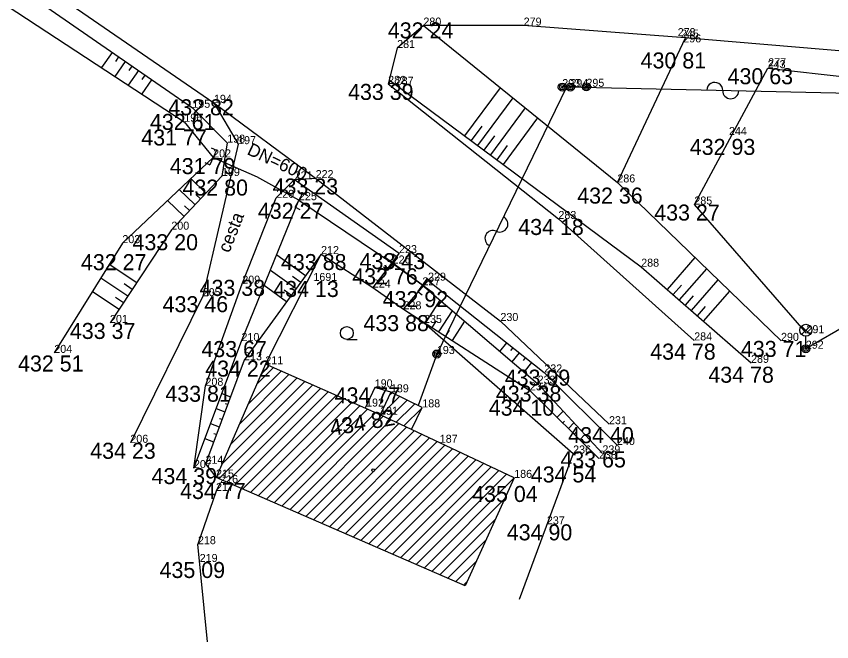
# Model space of a CAD drawing. Extents: x -559180 to -551373, y -1076947 to -1072071.
# Drawn here: x -554299 to -554248, y -1073863.4 to -1073824.3 of the extents above; entities that cross this region are included whole.
import ezdxf

# ---------------------------------------------------------------- set-up
doc = ezdxf.new("R2010")
doc.units = 0
for name, color, linetype in [('12_PLOTY', 7, 'Continuous'), ('14_BUDOVY', 7, 'Continuous'), ('17_KOMUNIKACE', 7, 'Continuous'), ('18_POLOHOPIS', 7, 'Continuous'), ('1_VODA_ZN', 7, 'Continuous'), ('20_EL_ZN', 7, 'Continuous'), ('26_SRAFY', 7, 'Continuous'), ('27_HRANA_PATA', 7, 'Continuous'), ('30_SDEL_ZN', 7, 'Continuous'), ('31_SDELOVACI', 7, 'Continuous'), ('32', 7, 'Continuous'), ('3_BODY', 7, 'Continuous'), ('40_KANAL_ZN', 7, 'Continuous'), ('45_ZN_KULTURY', 7, 'Continuous'), ('47_ZN_STAV_OBJ$', 7, 'Continuous'), ('49_POPIS_KANAL', 7, 'Continuous'), ('52_POPIS_UCELOVY', 7, 'Continuous'), ('6_VYSKY', 7, 'Continuous'), ('NNnadzemní', 7, 'Continuous')]:
    doc.layers.add(name, color=color, linetype=linetype)

# ---------------------------------------------------------------- blocks, each defined once
blk = doc.blocks.new('POINT_DISPLAY')
blk.add_line((0, 0), (0, 0))
blk = doc.blocks.new('SLDP')
at = {"layer": '20_EL_ZN'}
for radius in [0.25, 0.158, 0.05]:
    blk.add_circle((0, 0), radius, dxfattribs=at)
blk = doc.blocks.new('JS600')
at = {"layer": '49_POPIS_KANAL'}
blk.add_text('DN=600', height=0.8, rotation=0, dxfattribs=at).set_placement((0.752, -0.172))
blk = doc.blocks.new('LAO')
at = {"layer": '20_EL_ZN'}
for p, q in [((-0.265, 1.415), (0.265, 0.885)), ((-0.265, 0.885), (0.265, 1.415)), ((0, 0), (0, 0.775))]:
    blk.add_line(p, q, dxfattribs=at)
blk.add_circle((0, 1.15), 0.375, dxfattribs=at)
blk = doc.blocks.new('BZ')
at = {"layer": '47_ZN_STAV_OBJ$'}
blk.add_circle((0, 0), 0.0875, dxfattribs=at)
blk = doc.blocks.new('VYUST')
at = {"layer": '40_KANAL_ZN'}
for p, q in [((-0.35, 0.5), (0, 0.5)), ((0, 0.5), (0, -0.5)), ((0, 0), (3, 0.001)), ((-0.35, -0.5), (0, -0.5))]:
    blk.add_line(p, q, dxfattribs=at)
blk = doc.blocks.new('ZAHRAD')
at = {"layer": '45_ZN_KULTURY'}
blk.add_line((0, 0), (0.65, 0.003), dxfattribs=at)
blk.add_circle((0, 0.403), 0.403, dxfattribs=at)
blk = doc.blocks.new('SDEN')
at = {"layer": '30_SDEL_ZN'}
for centre, start, end in [((0.5, 0), 359.9999, 179.9999), ((1.5, 0), 179.9999, 359.9999)]:
    blk.add_arc(centre, 0.5, start, end, dxfattribs=at)

msp = doc.modelspace()

# ---------------------------------------------------------------- linework, layer by layer
at = {"layer": '12_PLOTY'}
for p, q in [((-554256.62, -1073836.08), (-554252.04, -1073827.57)), ((-554252.04, -1073827.57), (-554236.91, -1073829.29)), ((-554249.62, -1073844.11), (-554256.62, -1073836.08)), ((-554283.41, -1073846.05), (-554279.93, -1073839.17)), ((-554279.93, -1073839.17), (-554276.7, -1073841.26)), ((-554276.7, -1073841.26), (-554274.78, -1073842.62)), ((-554274.78, -1073842.62), (-554273.5, -1073843.47)), ((-554273.5, -1073843.47), (-554264.19, -1073851.62)), ((-554264.19, -1073851.62), (-554267.569, -1073860.727)), ((-554286.23, -1073853.46), (-554286.49, -1073853.96)), ((-554286.49, -1073853.96), (-554287.62, -1073857.28)), ((-554287.017, -1073863.365), (-554287.62, -1073857.28))]:
    msp.add_line(p, q, dxfattribs=at)
at = {"layer": '14_BUDOVY'}
for p, q in [((-554283.41, -1073846.05), (-554286.49, -1073853.12)), ((-554276.25, -1073849.2), (-554283.41, -1073846.05)), ((-554275.57, -1073847.8), (-554276.25, -1073849.2)), ((-554273.61, -1073848.74), (-554275.57, -1073847.8)), ((-554274.274, -1073850.124), (-554273.61, -1073848.74)), ((-554274.274, -1073850.124), (-554276.25, -1073849.2)), ((-554267.87, -1073853.14), (-554274.274, -1073850.124)), ((-554270.94, -1073859.88), (-554286.49, -1073853.12)), ((-554267.87, -1073853.14), (-554270.94, -1073859.88))]:
    msp.add_line(p, q, dxfattribs=at)
at = {"layer": '17_KOMUNIKACE'}
for p, q in [((-554320.63, -1073806.35), (-554286.62, -1073829.73)), ((-554273.54, -1073824.91), (-554275.18, -1073826.31)), ((-554267.28, -1073824.91), (-554273.54, -1073824.91)), ((-554257.46, -1073825.66), (-554267.28, -1073824.91)), ((-554236.82, -1073827.4), (-554257.46, -1073825.66)), ((-554275.18, -1073826.31), (-554275.74, -1073828.55)), ((-554275.74, -1073828.55), (-554265.11, -1073836.98)), ((-554286.62, -1073829.73), (-554285.11, -1073832.31)), ((-554286.62, -1073829.73), (-554280.27, -1073834.43)), ((-554285.11, -1073832.31), (-554287.32, -1073841.8)), ((-554282.73, -1073835.66), (-554281.58, -1073834.51)), ((-554281.58, -1073834.51), (-554280.27, -1073834.43)), ((-554280.27, -1073834.43), (-554268.73, -1073843.35)), ((-554284.85, -1073841.02), (-554282.73, -1073835.66)), ((-554265.11, -1073836.98), (-554256.63, -1073844.56)), ((-554287.15, -1073847.39), (-554284.85, -1073841.02)), ((-554287.32, -1073841.8), (-554291.84, -1073850.95)), ((-554268.73, -1073843.35), (-554261.95, -1073849.79)), ((-554287.87, -1073852.53), (-554287.15, -1073847.39))]:
    msp.add_line(p, q, dxfattribs=at)
at = {"layer": '18_POLOHOPIS'}
for p, q in [((-554276.58, -1073847.49), (-554277.168, -1073848.796)), ((-554275.57, -1073847.8), (-554276.58, -1073847.49))]:
    msp.add_line(p, q, dxfattribs=at)
at = {"layer": '26_SRAFY'}
for p, q in [((-554293.621, -1073827.532), (-554292.964, -1073826.583)), ((-554292.748, -1073827.149), (-554292.553, -1073826.867)), ((-554292.785, -1073828.081), (-554292.142, -1073827.152)), ((-554291.921, -1073827.712), (-554291.73, -1073827.437)), ((-554291.948, -1073828.629), (-554291.319, -1073827.721)), ((-554291.095, -1073828.275), (-554290.908, -1073828.006)), ((-554291.112, -1073829.178), (-554290.497, -1073828.29)), ((-554268.741, -1073828.789), (-554270.965, -1073831.79)), ((-554267.963, -1073829.419), (-554270.161, -1073832.386)), ((-554267.184, -1073830.048), (-554269.358, -1073832.981)), ((-554266.406, -1073830.677), (-554268.555, -1073833.576)), ((-554269.9, -1073831.193), (-554270.563, -1073832.088)), ((-554269.104, -1073831.798), (-554269.76, -1073832.683)), ((-554268.308, -1073832.404), (-554268.956, -1073833.279)), ((-554288.071, -1073834.462), (-554287.119, -1073835.36)), ((-554288.8, -1073835.149), (-554287.806, -1073836.087)), ((-554287.754, -1073835.448), (-554287.463, -1073835.723)), ((-554289.528, -1073835.837), (-554288.492, -1073836.814)), ((-554288.453, -1073836.163), (-554288.149, -1073836.451)), ((-554282.7, -1073839.214), (-554280.906, -1073840.515)), ((-554293.157, -1073839.807), (-554291.442, -1073840.936)), ((-554256.586, -1073839.388), (-554258.323, -1073841.374)), ((-554283.089, -1073840.167), (-554281.493, -1073841.325)), ((-554255.866, -1073840.084), (-554257.57, -1073842.033)), ((-554293.684, -1073840.657), (-554291.992, -1073841.771)), ((-554281.708, -1073840.551), (-554281.2, -1073840.92)), ((-554255.147, -1073840.781), (-554256.817, -1073842.691)), ((-554292.228, -1073841.017), (-554291.717, -1073841.353)), ((-554283.479, -1073841.12), (-554282.081, -1073842.134)), ((-554257.43, -1073841.113), (-554257.946, -1073841.704)), ((-554294.212, -1073841.507), (-554292.542, -1073842.606)), ((-554292.771, -1073841.857), (-554292.267, -1073842.189)), ((-554282.236, -1073841.404), (-554281.787, -1073841.73)), ((-554256.688, -1073841.783), (-554257.194, -1073842.362)), ((-554254.427, -1073841.477), (-554256.065, -1073843.349)), ((-554272.511, -1073842.05), (-554273.431, -1073843.485)), ((-554271.743, -1073842.705), (-554272.59, -1073844.025)), ((-554255.945, -1073842.453), (-554256.441, -1073843.02)), ((-554272.745, -1073843.342), (-554273.01, -1073843.755)), ((-554270.976, -1073843.361), (-554271.748, -1073844.565)), ((-554271.926, -1073843.916), (-554272.169, -1073844.295)), ((-554268.762, -1073845.251), (-554268.335, -1073844.709)), ((-554268.074, -1073845.186), (-554267.942, -1073845.019)), ((-554268.001, -1073845.901), (-554267.55, -1073845.329)), ((-554267.296, -1073845.815), (-554267.157, -1073845.639)), ((-554267.24, -1073846.551), (-554266.765, -1073845.949)), ((-554286.128, -1073847.879), (-554285.59, -1073848.08)), ((-554285.927, -1073848.488), (-554285.765, -1073848.548)), ((-554286.479, -1073848.815), (-554285.94, -1073849.016)), ((-554264.819, -1073848.968), (-554265.198, -1073849.352)), ((-554286.277, -1073849.425), (-554286.115, -1073849.485)), ((-554286.83, -1073849.752), (-554286.289, -1073849.953)), ((-554264.733, -1073849.593), (-554264.843, -1073849.703)), ((-554264.137, -1073849.701), (-554264.487, -1073850.055)), ((-554286.626, -1073850.361), (-554286.464, -1073850.422)), ((-554264.031, -1073850.305), (-554264.132, -1073850.406)), ((-554263.455, -1073850.433), (-554263.776, -1073850.758)), ((-554287.18, -1073850.688), (-554286.639, -1073850.89))]:
    msp.add_line(p, q, dxfattribs=at)
at = {"layer": '27_HRANA_PATA'}
for p, q in [((-554326.55, -1073803.33), (-554287.97, -1073830.04)), ((-554327.69, -1073805.19), (-554288.47, -1073830.91)), ((-554273.54, -1073824.91), (-554261.43, -1073834.7)), ((-554261.43, -1073834.7), (-554257.18, -1073825.684)), ((-554275.677, -1073828.298), (-554259.94, -1073839.96)), ((-554287.97, -1073830.04), (-554285.79, -1073832.22)), ((-554288.47, -1073830.91), (-554286.67, -1073833.14)), ((-554285.79, -1073832.22), (-554286.12, -1073834.3)), ((-554286.67, -1073833.14), (-554292.34, -1073838.49)), ((-554286.12, -1073834.3), (-554289.28, -1073837.65)), ((-554281.58, -1073834.51), (-554275.06, -1073839.11)), ((-554261.43, -1073834.7), (-554251.21, -1073844.59)), ((-554284.9, -1073844.6), (-554281.31, -1073835.81)), ((-554281.31, -1073835.81), (-554275.46, -1073839.76)), ((-554289.28, -1073837.65), (-554293.11, -1073843.47)), ((-554292.34, -1073838.49), (-554296.59, -1073845.34)), ((-554279.93, -1073839.17), (-554284.74, -1073845.8)), ((-554275.06, -1073839.11), (-554276.7, -1073841.26)), ((-554259.94, -1073839.96), (-554253.08, -1073845.96)), ((-554274.78, -1073842.62), (-554273.25, -1073840.83)), ((-554273.25, -1073840.83), (-554265.99, -1073846.56)), ((-554273.6, -1073841.12), (-554266.41, -1073847.26)), ((-554274.78, -1073842.62), (-554266.89, -1073847.68)), ((-554287.87, -1073852.53), (-554284.9, -1073844.6)), ((-554284.74, -1073845.8), (-554287.15, -1073852.26)), ((-554265.99, -1073846.56), (-554261.45, -1073851.09)), ((-554266.41, -1073847.26), (-554262.36, -1073851.61)), ((-554266.89, -1073847.68), (-554262.58, -1073851.94)), ((-554287.15, -1073852.26), (-554286.49, -1073853.12))]:
    msp.add_line(p, q, dxfattribs=at)
at = {"layer": '31_SDELOVACI'}
for p, q in [((-554264.61, -1073828.75), (-554272.7, -1073845.41)), ((-554220.52, -1073829.72), (-554264.61, -1073828.75)), ((-554272.7, -1073845.41), (-554273.859, -1073848.621))]:
    msp.add_line(p, q, dxfattribs=at)
at = {"layer": '32'}
for p, q in [((-554284.502, -1073848.556), (-554282.428, -1073846.482)), ((-554283.956, -1073847.303), (-554282.919, -1073846.266)), ((-554285.593, -1073851.062), (-554281.446, -1073846.914)), ((-554285.048, -1073849.809), (-554281.937, -1073846.698)), ((-554286.314, -1073853.197), (-554280.464, -1073847.346)), ((-554286.139, -1073852.315), (-554280.955, -1073847.13)), ((-554285.821, -1073853.411), (-554279.973, -1073847.562)), ((-554285.328, -1073853.625), (-554279.481, -1073847.778)), ((-554284.835, -1073853.839), (-554278.99, -1073847.994)), ((-554275.65, -1073847.964), (-554275.513, -1073847.827)), ((-554284.343, -1073854.054), (-554278.499, -1073848.21)), ((-554283.85, -1073854.268), (-554278.008, -1073848.426)), ((-554276.201, -1073849.223), (-554275.035, -1073848.057)), ((-554274.812, -1073848.54), (-554274.557, -1073848.286)), ((-554274.205, -1073848.641), (-554274.079, -1073848.515)), ((-554283.357, -1073854.482), (-554277.517, -1073848.642)), ((-554282.864, -1073854.696), (-554277.026, -1073848.859)), ((-554275.719, -1073849.448), (-554274.812, -1073848.54)), ((-554275.238, -1073849.673), (-554274.205, -1073848.641)), ((-554274.756, -1073849.899), (-554273.622, -1073848.765)), ((-554282.371, -1073854.911), (-554276.535, -1073849.075)), ((-554281.878, -1073855.125), (-554276.048, -1073849.295)), ((-554281.385, -1073855.339), (-554275.566, -1073849.52)), ((-554280.893, -1073855.553), (-554275.084, -1073849.745)), ((-554280.4, -1073855.768), (-554274.602, -1073849.97)), ((-554279.907, -1073855.982), (-554274.121, -1073850.196)), ((-554279.414, -1073856.196), (-554273.64, -1073850.422)), ((-554278.921, -1073856.41), (-554273.16, -1073850.649)), ((-554278.428, -1073856.625), (-554272.679, -1073850.875)), ((-554277.935, -1073856.839), (-554272.198, -1073851.102)), ((-554277.443, -1073857.053), (-554271.717, -1073851.328)), ((-554276.95, -1073857.267), (-554271.237, -1073851.554)), ((-554276.457, -1073857.482), (-554270.756, -1073851.781)), ((-554275.964, -1073857.696), (-554270.275, -1073852.007)), ((-554275.471, -1073857.91), (-554269.795, -1073852.234)), ((-554274.978, -1073858.124), (-554269.314, -1073852.46)), ((-554274.485, -1073858.339), (-554268.833, -1073852.686)), ((-554273.993, -1073858.553), (-554268.352, -1073852.913)), ((-554273.5, -1073858.767), (-554267.872, -1073853.139)), ((-554273.007, -1073858.981), (-554268.459, -1073854.434)), ((-554272.514, -1073859.196), (-554269.051, -1073855.732)), ((-554272.021, -1073859.41), (-554269.642, -1073857.031)), ((-554271.528, -1073859.624), (-554270.234, -1073858.33)), ((-554271.036, -1073859.838), (-554270.825, -1073859.628))]:
    msp.add_line(p, q, dxfattribs=at)
at = {"layer": 'NNnadzemní'}
msp.add_line((-554214.59, -1073824.79), (-554249.66, -1073845.08), dxfattribs=at)

# ---------------------------------------------------------------- block references
at = {"layer": '1_VODA_ZN'}
for p in [(-554273.54, -1073824.91), (-554267.28, -1073824.91), (-554257.66, -1073825.57), (-554257.46, -1073825.66), (-554257.31, -1073825.96), (-554275.18, -1073826.31), (-554252.04, -1073827.57), (-554252.01, -1073827.45), (-554275.74, -1073828.55), (-554275.27, -1073828.6), (-554264.87, -1073828.75), (-554264.36, -1073828.75), (-554263.36, -1073828.73), (-554287.97, -1073830.04), (-554286.62, -1073829.73), (-554288.47, -1073830.91), (-554285.79, -1073832.22), (-554254.46, -1073831.74), (-554285.11, -1073832.31), (-554286.67, -1073833.14), (-554286.12, -1073834.3), (-554281.58, -1073834.51), (-554280.27, -1073834.43), (-554261.43, -1073834.7), (-554282.73, -1073835.66), (-554281.31, -1073835.81), (-554256.62, -1073836.08), (-554265.11, -1073836.98), (-554289.28, -1073837.65), (-554292.34, -1073838.49), (-554279.93, -1073839.17), (-554275.06, -1073839.11), (-554275.46, -1073839.76), (-554259.94, -1073839.96), (-554280.41, -1073840.85), (-554273.25, -1073840.83), (-554284.85, -1073841.02), (-554276.7, -1073841.26), (-554273.6, -1073841.12), (-554287.32, -1073841.8), (-554274.78, -1073842.62), (-554268.73, -1073843.35), (-554293.11, -1073843.47), (-554273.5, -1073843.47), (-554249.62, -1073844.11), (-554284.9, -1073844.6), (-554256.63, -1073844.56), (-554251.21, -1073844.59), (-554296.59, -1073845.34), (-554272.7, -1073845.41), (-554249.66, -1073845.08), (-554284.74, -1073845.8), (-554253.08, -1073845.96), (-554283.41, -1073846.05), (-554265.99, -1073846.56), (-554287.15, -1073847.39), (-554276.58, -1073847.49), (-554266.41, -1073847.26), (-554275.57, -1073847.8), (-554266.89, -1073847.68), (-554277.12, -1073848.69), (-554273.61, -1073848.74), (-554276.25, -1073849.2), (-554261.95, -1073849.79), (-554291.84, -1073850.95), (-554272.52, -1073850.95), (-554261.45, -1073851.09), (-554264.19, -1073851.62), (-554262.58, -1073851.94), (-554262.36, -1073851.61), (-554287.87, -1073852.53), (-554287.15, -1073852.26), (-554286.49, -1073853.12), (-554286.23, -1073853.46), (-554267.87, -1073853.14), (-554267.86, -1073853.16), (-554267.86, -1073853.16), (-554286.49, -1073853.96), (-554265.83, -1073856.04), (-554287.62, -1073857.28), (-554287.51, -1073858.39)]:
    msp.add_blockref('POINT_DISPLAY', p, dxfattribs=at)
at = {"layer": '20_EL_ZN'}
for name, p in [('SLDP', (-554264.87, -1073828.75)), ('SLDP', (-554264.36, -1073828.75)), ('SLDP', (-554263.36, -1073828.73)), ('LAO', (-554249.66, -1073845.08)), ('SLDP', (-554249.66, -1073845.08)), ('SLDP', (-554272.7, -1073845.41))]:
    msp.add_blockref(name, p, dxfattribs=at)
at = {"layer": '30_SDEL_ZN'}
for p, xscale, yscale, rotation in [((-554255.85, -1073828.943), 0.9999997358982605, 0.9999997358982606, -1.2602206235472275), ((-554269.415, -1073838.645), 1.0000003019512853, 1.0000003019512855, 64.099210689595)]:
    msp.add_blockref('SDEN', p, dxfattribs=dict(at, xscale=xscale, yscale=yscale, rotation=rotation))
at = {"layer": '32'}
for p in [(-554283.41, -1073846.05), (-554274.812, -1073848.54), (-554274.205, -1073848.641)]:
    msp.add_blockref('POINT_DISPLAY', p, dxfattribs=at)
at = {"layer": '40_KANAL_ZN'}
for p, xscale, yscale, rotation in [((-554286.67, -1073833.14), 0.9999997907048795, 0.9999997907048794, -23.947481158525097), ((-554281.31, -1073835.81), 1.0000023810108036, 1.0000023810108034, 151.05768264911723), ((-554273.6, -1073841.12), 1.0000013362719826, 1.0000013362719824, 143.35720682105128), ((-554275.46, -1073839.76), 0.9999999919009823, 0.9999999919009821, -35.769580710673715)]:
    msp.add_blockref('VYUST', p, dxfattribs=dict(at, xscale=xscale, yscale=yscale, rotation=rotation))
at = {"layer": '45_ZN_KULTURY'}
msp.add_blockref('ZAHRAD', (-554278.325, -1073844.503), dxfattribs=at)
at = {"layer": '47_ZN_STAV_OBJ$'}
msp.add_blockref('BZ', (-554276.68, -1073852.669), dxfattribs=at)
at = {"layer": '49_POPIS_KANAL', "xscale": 0.999997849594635, "yscale": 0.9999978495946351, "rotation": -25.25720187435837}
msp.add_blockref('JS600', (-554285.215, -1073832.442), dxfattribs=at)

# ---------------------------------------------------------------- texts
at = {"layer": '3_BODY'}
for s, p in [('280', (-554273.54, -1073824.91)), ('279', (-554267.28, -1073824.91)), ('278', (-554257.66, -1073825.57)), ('245', (-554257.46, -1073825.66)), ('296', (-554257.31, -1073825.96)), ('281', (-554275.18, -1073826.31)), ('243', (-554252.04, -1073827.57)), ('277', (-554252.01, -1073827.45)), ('282', (-554275.74, -1073828.55)), ('287', (-554275.27, -1073828.6)), ('293', (-554264.87, -1073828.75)), ('294', (-554264.36, -1073828.75)), ('295', (-554263.36, -1073828.73)), ('195', (-554287.97, -1073830.04)), ('194', (-554286.62, -1073829.73)), ('196', (-554288.47, -1073830.91)), ('198', (-554285.79, -1073832.22)), ('244', (-554254.46, -1073831.74)), ('197', (-554285.11, -1073832.31)), ('202', (-554286.67, -1073833.14)), ('199', (-554286.12, -1073834.3)), ('221', (-554281.58, -1073834.51)), ('222', (-554280.27, -1073834.43)), ('286', (-554261.43, -1073834.7)), ('220', (-554282.73, -1073835.66)), ('225', (-554281.31, -1073835.81)), ('285', (-554256.62, -1073836.08)), ('283', (-554265.11, -1073836.98)), ('200', (-554289.28, -1073837.65)), ('203', (-554292.34, -1073838.49)), ('212', (-554279.93, -1073839.17)), ('223', (-554275.06, -1073839.11)), ('226', (-554275.46, -1073839.76)), ('288', (-554259.94, -1073839.96)), ('1691', (-554280.41, -1073840.85)), ('229', (-554273.25, -1073840.83)), ('209', (-554284.85, -1073841.02)), ('224', (-554276.7, -1073841.26)), ('227', (-554273.6, -1073841.12)), ('205', (-554287.32, -1073841.8)), ('228', (-554274.78, -1073842.62)), ('230', (-554268.73, -1073843.35)), ('201', (-554293.11, -1073843.47)), ('235', (-554273.5, -1073843.47)), ('291', (-554249.62, -1073844.11)), ('210', (-554284.9, -1073844.6)), ('284', (-554256.63, -1073844.56)), ('290', (-554251.21, -1073844.59)), ('204', (-554296.59, -1073845.34)), ('193', (-554272.7, -1073845.41)), ('292', (-554249.66, -1073845.08)), ('213', (-554284.74, -1073845.8)), ('289', (-554253.08, -1073845.96)), ('211', (-554283.41, -1073846.05)), ('232', (-554265.99, -1073846.56)), ('208', (-554287.15, -1073847.39)), ('190', (-554276.58, -1073847.49)), ('233', (-554266.41, -1073847.26)), ('189', (-554275.57, -1073847.8)), ('234', (-554266.89, -1073847.68)), ('192', (-554277.12, -1073848.69)), ('188', (-554273.61, -1073848.74)), ('191', (-554276.25, -1073849.2)), ('231', (-554261.95, -1073849.79)), ('206', (-554291.84, -1073850.95)), ('187', (-554272.52, -1073850.95)), ('240', (-554261.45, -1073851.09)), ('236', (-554264.19, -1073851.62)), ('238', (-554262.58, -1073851.94)), ('239', (-554262.36, -1073851.61)), ('207', (-554287.87, -1073852.53)), ('214', (-554287.15, -1073852.26)), ('215', (-554286.49, -1073853.12)), ('216', (-554286.23, -1073853.46)), ('186', (-554267.87, -1073853.14)), ('217', (-554286.49, -1073853.96)), ('237', (-554265.83, -1073856.04)), ('218', (-554287.62, -1073857.28)), ('219', (-554287.51, -1073858.39))]:
    msp.add_text(s, height=0.5, dxfattribs=at).set_placement(p)
at = {"layer": '52_POPIS_UCELOVY'}
msp.add_text('cesta', height=0.8, rotation=68.4201, dxfattribs=at).set_placement((-554285.663, -1073839.14))
at = {"layer": '6_VYSKY'}
for s, p in [('432 24', (-554275.763, -1073825.708)), ('430 81', (-554259.977, -1073827.586)), ('430 63', (-554254.545, -1073828.57)), ('433 39', (-554278.245, -1073829.55)), ('432 82', (-554289.468, -1073830.509)), ('432 61', (-554290.616, -1073831.423)), ('431 77', (-554291.156, -1073832.394)), ('432 93', (-554256.905, -1073832.982)), ('431 79', (-554289.376, -1073834.18)), ('432 80', (-554288.584, -1073835.522)), ('433 23', (-554282.956, -1073835.45)), ('432 36', (-554263.935, -1073836.022)), ('432 27', (-554283.876, -1073836.971)), ('433 27', (-554259.125, -1073837.08)), ('434 18', (-554267.615, -1073837.98)), ('433 20', (-554291.705, -1073838.932)), ('432 27', (-554294.926, -1073840.176)), ('433 88', (-554282.435, -1073840.17)), ('433 43', (-554277.524, -1073840.11)), ('432 76', (-554277.985, -1073841.062)), ('433 38', (-554287.516, -1073841.778)), ('434 13', (-554282.915, -1073841.85)), ('434 13', (-554282.915, -1073841.85)), ('433 46', (-554289.825, -1073842.8)), ('432 92', (-554276.084, -1073842.483)), ('433 88', (-554277.285, -1073843.983)), ('433 37', (-554295.615, -1073844.47)), ('433 67', (-554287.405, -1073845.6)), ('434 78', (-554259.377, -1073845.762)), ('433 71', (-554253.715, -1073845.59)), ('432 51', (-554298.853, -1073846.501)), ('434 22', (-554287.164, -1073846.82)), ('433 99', (-554268.461, -1073847.385)), ('434 78', (-554255.746, -1073847.203)), ('433 81', (-554289.655, -1073848.39)), ('434 77', (-554279.085, -1073848.49)), ('433 38', (-554269.016, -1073848.38)), ('434 10', (-554269.461, -1073849.259)), ('434 40', (-554264.495, -1073850.972)), ('434 23', (-554294.345, -1073851.95)), ('433 65', (-554264.986, -1073852.489)), ('434 39', (-554290.517, -1073853.53)), ('434 54', (-554266.837, -1073853.427)), ('434 77', (-554288.735, -1073854.46)), ('435 04', (-554270.496, -1073854.645)), ('434 90', (-554268.335, -1073857.04)), ('435 09', (-554290.015, -1073859.39))]:
    msp.add_text(s, height=1, dxfattribs=at).set_placement(p)
msp.add_text('434 82', height=1, rotation=10.0548, dxfattribs=at).set_placement((-554279.281, -1073850.537))

doc.saveas('drawing.dxf')
